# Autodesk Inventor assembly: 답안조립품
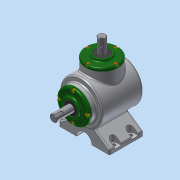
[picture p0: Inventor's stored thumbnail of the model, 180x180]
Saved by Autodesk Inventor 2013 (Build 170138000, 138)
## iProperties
Created: 2017-04
Part Number: 답안조립품
Document SubType Name: Assembly
Designer: dgall
Author: dgall
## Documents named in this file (14)
- C:\Users\dgall\Desktop\470407V1018\답안조립품.iam
- C:\Users\dgall\Desktop\470407V1018\본체.ipt
- C:\Users\dgall\Desktop\470407V1018\메인 베벨기어.ipt
- C:\Users\dgall\Desktop\470407V1018\메인 축.ipt
- 메인 축.ipt
- C:\Users\dgall\Desktop\470407V1018\베어링 6203.ipt
- C:\Users\dgall\Desktop\470407V1018\볼트 M4.ipt
- C:\Users\dgall\Desktop\470407V1018\서브 베벨기어.ipt
- C:\Users\dgall\Desktop\470407V1018\서브 축.ipt
- 서브 축.ipt
- C:\Users\dgall\Desktop\470407V1018\오일실 17 32 8.ipt
- C:\Users\dgall\Desktop\470407V1018\커버.ipt
- C:\Users\dgall\Desktop\470407V1018\키 4x4.ipt
- C:\Users\dgall\Desktop\470407V1018\키 5x5.ipt
